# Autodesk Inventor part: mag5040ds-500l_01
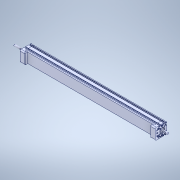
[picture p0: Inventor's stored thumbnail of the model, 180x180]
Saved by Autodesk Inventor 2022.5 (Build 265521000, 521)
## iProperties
Created: 2023-04
Part Number: mag5040ds-500l_01
Material: Generic
Document SubType Name: Modeling
Designer: ImaoCorp
Density: 1 g/cm^3
Appearance: Default
Author: ImaoCorp
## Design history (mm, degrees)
feature "mag5040ds-500l_01"
node "ソリッド1"
